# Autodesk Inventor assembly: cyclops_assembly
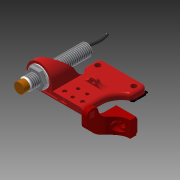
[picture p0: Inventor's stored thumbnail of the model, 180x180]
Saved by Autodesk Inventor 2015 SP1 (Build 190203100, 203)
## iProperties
Created: 2015-11
Part Number: cyclops_assembly
Document SubType Name: Assembly
Designer: egor
Author: egor
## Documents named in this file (7)
- D:\Dropbox\3D printers\Models\Inventor Models\K8200_Improvements\cyclops_assembly.iam
- D:\Dropbox\3D printers\Models\Inventor Models\K8200_Improvements\Cyclops_holder.ipt
- D:\Dropbox\3D printers\Models\Inventor Models\K8200_Improvements\Cyclops_holder_support.ipt
- D:\Dropbox\3D printers\Models\Inventor Models\K8200_Improvements\Cyclops_rail.ipt
- D:\Dropbox\3D printers\Models\Inventor Models\K8200_Improvements\inductive_sensor.ipt
- D:\Dropbox\3D printers\Models\Inventor Models\K8200_Improvements\DIN 6797 - J 13.ipt
- D:\Dropbox\3D printers\Models\Inventor Models\K8200_Improvements\sensor nut M12.ipt
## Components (7 placed, 6 different names)
1. Cyclops_holder:1 — Mate:1, Mate:2, Flush:1, Mate:3, Mate:4, Mate:5, Mate:6, Flush:2, Angle:1, Angle:2, Mate:8, Angle:5, Mate:11
2. Cyclops_holder_support:1 — Mate:1, Mate:2, Flush:1
3. Cyclops_rail:1 — Mate:3, Mate:4, Mate:5
4. inductive_sensor:1 — Mate:6, Flush:2, Angle:1, Angle:2, Mate:7, Angle:3, Angle:4, Mate:9, Mate:10, Angle:6, Angle:7
5. DIN 6797 - J 13:1 — Mate:7, Mate:8, Angle:3, Angle:4, Mate:12
6. sensor nut M12:1 — Mate:9, Angle:6, Angle:7, Mate:12
7. sensor nut M12:2 — Mate:10, Angle:5, Mate:11
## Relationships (21: Mate 12, Angle 7, Flush 2)
- Mate:1: Cyclops_holder:1 ↔ Cyclops_holder_support:1
- Mate:2: Cyclops_holder:1 ↔ Cyclops_holder_support:1
- Flush:1: Cyclops_holder:1 ↔ Cyclops_holder_support:1
- Mate:3: Cyclops_holder:1 ↔ Cyclops_rail:1
- Mate:4: Cyclops_holder:1 ↔ Cyclops_rail:1
- Mate:5: Cyclops_holder:1 ↔ Cyclops_rail:1
- Mate:6: Cyclops_holder:1 ↔ inductive_sensor:1
- Flush:2: Cyclops_holder:1 ↔ inductive_sensor:1
- Angle:1: Cyclops_holder:1 ↔ inductive_sensor:1
- Angle:2: Cyclops_holder:1 ↔ inductive_sensor:1
- Mate:7: inductive_sensor:1 ↔ DIN 6797 - J 13:1
- Mate:8: Cyclops_holder:1 ↔ DIN 6797 - J 13:1
- Angle:3: inductive_sensor:1 ↔ DIN 6797 - J 13:1
- Angle:4: inductive_sensor:1 ↔ DIN 6797 - J 13:1
- Mate:9: inductive_sensor:1 ↔ sensor nut M12:1
- Mate:10: inductive_sensor:1 ↔ sensor nut M12:2
- Angle:5: Cyclops_holder:1 ↔ sensor nut M12:2
- Mate:11: Cyclops_holder:1 ↔ sensor nut M12:2
- Angle:6: inductive_sensor:1 ↔ sensor nut M12:1
- Angle:7: inductive_sensor:1 ↔ sensor nut M12:1
- Mate:12: DIN 6797 - J 13:1 ↔ sensor nut M12:1
